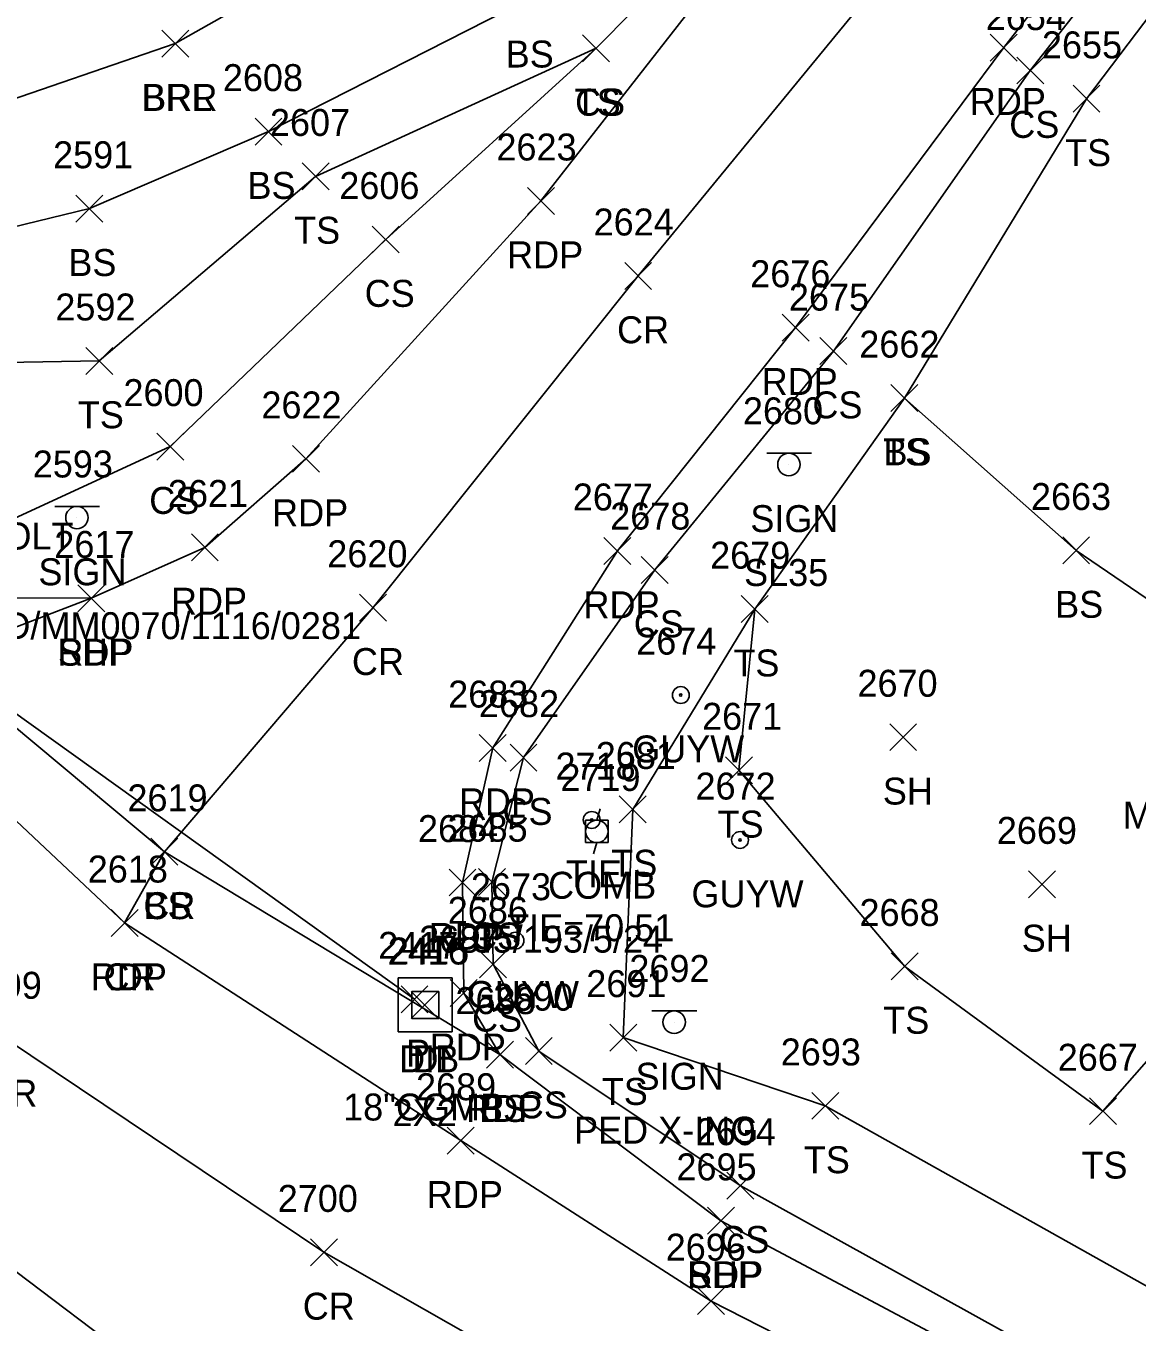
# Model space of a CAD drawing. Extents: x 1504228 to 1506103, y 437717 to 440106.
# Drawn here: x 1505331 to 1505413.5, y 438079.5 to 438175.7 of the extents above; entities that cross this region are included whole.
import ezdxf

# ---------------------------------------------------------------- set-up
doc = ezdxf.new("R2010")
doc.units = 0
for name, color, linetype in [('C_A', 7, 'Continuous'), ('C_C', 7, 'Continuous'), ('C_I', 7, 'Continuous'), ('CBP', 7, 'Continuous'), ('D_A', 7, 'Continuous'), ('D_C', 7, 'Continuous'), ('D_I', 7, 'Continuous'), ('D_TIC', 7, 'Continuous'), ('DCP', 7, 'Continuous'), ('DS', 7, 'Continuous'), ('L_A', 7, 'Continuous'), ('L_C', 7, 'Continuous'), ('L_I', 7, 'Continuous'), ('L_TIC', 7, 'Continuous'), ('LABL', 7, 'Continuous'), ('LELB', 7, 'Continuous'), ('P_A', 7, 'Continuous'), ('P_I', 7, 'Continuous'), ('P_TIC', 7, 'Continuous'), ('PET', 7, 'Continuous'), ('PRC', 7, 'Continuous'), ('PSP', 7, 'Continuous'), ('S_A', 7, 'Continuous'), ('S_C', 7, 'Continuous'), ('S_I', 7, 'Continuous'), ('SSGN', 7, 'Continuous'), ('U_A', 7, 'Continuous'), ('U_C', 7, 'Continuous'), ('U_I', 7, 'Continuous'), ('UP', 7, 'Continuous'), ('UPGW', 7, 'Continuous')]:
    doc.layers.add(name, color=color, linetype=linetype)

msp = doc.modelspace()

# ---------------------------------------------------------------- linework, layer by layer
at = {"layer": 'CBP'}
for radius in [0.625, 0.0833]:
    msp.add_circle((1505372.977, 438116.779), radius, dxfattribs=at)
at = {"layer": 'D_TIC'}
for points in [[(1505358.818, 438102.471), (1505360.818, 438104.471)], [(1505360.818, 438102.471), (1505358.818, 438104.471)], [(1505359.574, 438102.048), (1505361.574, 438104.048)], [(1505361.574, 438102.048), (1505359.574, 438104.048)]]:
    msp.add_lwpolyline(points, dxfattribs=at)
at = {"layer": 'DCP'}
msp.add_lwpolyline([(1505359.818, 438103.471), (1505323.404, 438129.556)], dxfattribs=at)
at = {"layer": 'DS'}
for p, q in [((1505358.613, 438105.05), (1505362.613, 438105.05)), ((1505358.613, 438101.05), (1505358.613, 438105.05)), ((1505362.613, 438105.05), (1505362.613, 438101.05)), ((1505359.613, 438102.05), (1505359.613, 438104.05)), ((1505359.613, 438104.05), (1505361.613, 438104.05)), ((1505361.613, 438104.05), (1505361.613, 438102.05)), ((1505360.618, 438103.052), (1505360.618, 438103.052)), ((1505360.618, 438103.052), (1505360.618, 438103.052)), ((1505361.613, 438102.05), (1505359.613, 438102.05)), ((1505362.613, 438101.05), (1505358.613, 438101.05))]:
    msp.add_line(p, q, dxfattribs=at)
at = {"layer": 'L_TIC'}
for points in [[(1505341.058, 438173.403), (1505343.058, 438175.403)], [(1505343.058, 438173.403), (1505341.058, 438175.403)], [(1505341.058, 438173.403), (1505343.058, 438175.403)], [(1505343.058, 438173.403), (1505341.058, 438175.403)], [(1505372.298, 438173.049), (1505374.298, 438175.049)], [(1505374.298, 438173.049), (1505372.298, 438175.049)], [(1505372.298, 438173.049), (1505374.298, 438175.049)], [(1505374.298, 438173.049), (1505372.298, 438175.049)], [(1505404.53, 438171.403), (1505406.53, 438173.403)], [(1505406.53, 438171.403), (1505404.53, 438173.403)], [(1505408.704, 438169.307), (1505410.704, 438171.307)], [(1505410.704, 438169.307), (1505408.704, 438171.307)], [(1505347.978, 438166.874), (1505349.978, 438168.874)], [(1505349.978, 438166.874), (1505347.978, 438168.874)], [(1505351.472, 438163.545), (1505353.472, 438165.545)], [(1505353.472, 438163.545), (1505351.472, 438165.545)], [(1505334.681, 438161.149), (1505336.681, 438163.149)], [(1505336.681, 438161.149), (1505334.681, 438163.149)], [(1505356.679, 438158.862), (1505358.679, 438160.862)], [(1505358.679, 438158.862), (1505356.679, 438160.862)], [(1505389.919, 438150.584), (1505391.919, 438152.584)], [(1505391.919, 438150.584), (1505389.919, 438152.584)], [(1505335.416, 438149.851), (1505337.416, 438151.851)], [(1505337.416, 438149.851), (1505335.416, 438151.851)], [(1505395.192, 438147.093), (1505397.192, 438149.093)], [(1505397.192, 438147.093), (1505395.192, 438149.093)], [(1505395.192, 438147.093), (1505397.192, 438149.093)], [(1505397.192, 438147.093), (1505395.192, 438149.093)], [(1505340.684, 438143.494), (1505342.684, 438145.494)], [(1505342.684, 438143.494), (1505340.684, 438145.494)], [(1505407.937, 438135.783), (1505409.937, 438137.783)], [(1505409.937, 438135.783), (1505407.937, 438137.783)], [(1505376.655, 438134.332), (1505378.655, 438136.332)], [(1505378.655, 438134.332), (1505376.655, 438136.332)], [(1505384.081, 438131.429), (1505386.081, 438133.429)], [(1505386.081, 438131.429), (1505384.081, 438133.429)], [(1505384.081, 438131.429), (1505386.081, 438133.429)], [(1505386.081, 438131.429), (1505384.081, 438133.429)], [(1505395.097, 438121.922), (1505397.097, 438123.922)], [(1505397.097, 438121.922), (1505395.097, 438123.922)], [(1505366.909, 438120.411), (1505368.909, 438122.411)], [(1505368.909, 438120.411), (1505366.909, 438122.411)], [(1505382.907, 438119.47), (1505384.907, 438121.47)], [(1505384.907, 438119.47), (1505382.907, 438121.47)], [(1505375.016, 438116.564), (1505377.016, 438118.564)], [(1505377.016, 438116.564), (1505375.016, 438118.564)], [(1505340.256, 438113.415), (1505342.256, 438115.415)], [(1505342.256, 438113.415), (1505340.256, 438115.415)], [(1505364.569, 438111.166), (1505366.569, 438113.166)], [(1505366.569, 438111.166), (1505364.569, 438113.166)], [(1505405.409, 438111.003), (1505407.409, 438113.003)], [(1505407.409, 438111.003), (1505405.409, 438113.003)], [(1505364.649, 438105.069), (1505366.649, 438107.069)], [(1505366.649, 438105.069), (1505364.649, 438107.069)], [(1505395.207, 438104.91), (1505397.207, 438106.91)], [(1505397.207, 438104.91), (1505395.207, 438106.91)], [(1505374.312, 438099.628), (1505376.312, 438101.628)], [(1505376.312, 438099.628), (1505374.312, 438101.628)], [(1505368.049, 438098.624), (1505370.049, 438100.624)], [(1505370.049, 438098.624), (1505368.049, 438100.624)], [(1505365.164, 438098.366), (1505367.164, 438100.366)], [(1505367.164, 438098.366), (1505365.164, 438100.366)], [(1505389.313, 438094.558), (1505391.313, 438096.558)], [(1505391.313, 438094.558), (1505389.313, 438096.558)], [(1505409.924, 438094.162), (1505411.924, 438096.162)], [(1505411.924, 438094.162), (1505409.924, 438096.162)], [(1505383, 438088.64), (1505385, 438090.64)], [(1505385, 438088.64), (1505383, 438090.64)]]:
    msp.add_lwpolyline(points, dxfattribs=at)
at = {"layer": 'LABL'}
for points in [[(1505412.94, 438279.434), (1505408.751, 438263.902), (1505393.358, 438239.3), (1505379.992, 438219.583), (1505364.652, 438204.996), (1505342.27, 438194.948), (1505325.182, 438184.758), (1505314.631, 438179.74), (1505312.566, 438178.307), (1505308.953, 438177.263), (1505304.583, 438176.7), (1505296.615, 438175.22), (1505299.292, 438169.398), (1505303.904, 438164.856), (1505308.252, 438160.874), (1505313.047, 438161.473), (1505317.495, 438164.603), (1505327.49, 438169.4), (1505342.058, 438174.403)], [(1505426.709, 438267.128), (1505407.768, 438230.9), (1505394.085, 438210.643), (1505390.776, 438201.917), (1505383.002, 438197.122), (1505370.464, 438191.891), (1505357.673, 438183.248), (1505342.058, 438174.403)]]:
    msp.add_lwpolyline(points, dxfattribs=at)
at = {"layer": 'LELB'}
for points in [[(1505464.371, 438267.578), (1505443.482, 438229.816), (1505429.783, 438207.884), (1505423.465, 438195.212), (1505405.53, 438172.403), (1505390.919, 438151.584), (1505377.655, 438135.332), (1505367.909, 438121.411), (1505365.569, 438112.166), (1505365.649, 438106.069), (1505369.049, 438099.624), (1505384, 438089.64), (1505418.55, 438070.496), (1505425.632, 438075.745)], [(1505470.06, 438267.163), (1505453.418, 438227.384), (1505434.759, 438206.384), (1505425.646, 438191.367), (1505409.704, 438170.307), (1505396.192, 438148.093), (1505385.081, 438132.429), (1505376.016, 438117.564), (1505375.312, 438100.628), (1505390.313, 438095.558), (1505425.632, 438075.745), (1505441.164, 438097.453)], [(1505460.601, 438222.447), (1505449.611, 438199.006), (1505434.468, 438180.022), (1505419.613, 438165.841), (1505418.197, 438153.284), (1505427.495, 438135.49), (1505434.259, 438123.437), (1505428.641, 438123.377), (1505423.022, 438108.926), (1505410.924, 438095.162), (1505396.207, 438105.91), (1505383.907, 438120.47), (1505385.081, 438132.429)], [(1505283.082, 438168.26), (1505293.755, 438159.929), (1505303.056, 438155.723), (1505307.447, 438154.511), (1505318.234, 438150.525), (1505336.416, 438150.851), (1505352.472, 438164.545), (1505373.298, 438174.049), (1505384.454, 438185.345), (1505390.057, 438193.61)], [(1505280.724, 438166.502), (1505281.778, 438166.802), (1505283.082, 438168.26), (1505285.843, 438169.435), (1505295.117, 438166.148), (1505307.071, 438157.841), (1505319.301, 438158.173), (1505335.681, 438162.149), (1505348.978, 438167.874), (1505368.148, 438177.626), (1505382.147, 438186.406), (1505384.268, 438190.42)], [(1505313.175, 438145.226), (1505328.105, 438138.232), (1505341.684, 438144.494), (1505357.679, 438159.862), (1505373.298, 438174.049)], [(1505396.192, 438148.093), (1505408.937, 438136.783), (1505428.641, 438123.377)], [(1505324.098, 438128.725), (1505341.256, 438114.415), (1505366.164, 438099.366)]]:
    msp.add_lwpolyline(points, dxfattribs=at)
at = {"layer": 'P_TIC'}
for points in [[(1505402.557, 438173.106), (1505404.557, 438175.106)], [(1505404.557, 438173.106), (1505402.557, 438175.106)], [(1505368.207, 438161.724), (1505370.207, 438163.724)], [(1505370.207, 438161.724), (1505368.207, 438163.724)], [(1505375.422, 438156.158), (1505377.422, 438158.158)], [(1505377.422, 438156.158), (1505375.422, 438158.158)], [(1505387.105, 438152.318), (1505389.105, 438154.318)], [(1505389.105, 438152.318), (1505387.105, 438154.318)], [(1505350.761, 438142.58), (1505352.761, 438144.58)], [(1505352.761, 438142.58), (1505350.761, 438144.58)], [(1505343.252, 438136.011), (1505345.252, 438138.011)], [(1505345.252, 438136.011), (1505343.252, 438138.011)], [(1505373.877, 438135.75), (1505375.877, 438137.75)], [(1505375.877, 438135.75), (1505373.877, 438137.75)], [(1505334.82, 438132.23), (1505336.82, 438134.23)], [(1505336.82, 438132.23), (1505334.82, 438134.23)], [(1505334.82, 438132.23), (1505336.82, 438134.23)], [(1505336.82, 438132.23), (1505334.82, 438134.23)], [(1505355.739, 438131.535), (1505357.739, 438133.535)], [(1505357.739, 438131.535), (1505355.739, 438133.535)], [(1505364.627, 438121.121), (1505366.627, 438123.121)], [(1505366.627, 438121.121), (1505364.627, 438123.121)], [(1505340.256, 438113.415), (1505342.256, 438115.415)], [(1505342.256, 438113.415), (1505340.256, 438115.415)], [(1505362.383, 438111.135), (1505364.383, 438113.135)], [(1505364.383, 438111.135), (1505362.383, 438113.135)], [(1505337.301, 438108.134), (1505339.301, 438110.134)], [(1505339.301, 438108.134), (1505337.301, 438110.134)], [(1505337.301, 438108.134), (1505339.301, 438110.134)], [(1505339.301, 438108.134), (1505337.301, 438110.134)], [(1505362.469, 438102.928), (1505364.469, 438104.928)], [(1505364.469, 438102.928), (1505362.469, 438104.928)], [(1505365.164, 438098.366), (1505367.164, 438100.366)], [(1505367.164, 438098.366), (1505365.164, 438100.366)], [(1505362.246, 438091.977), (1505364.246, 438093.977)], [(1505364.246, 438091.977), (1505362.246, 438093.977)], [(1505381.569, 438086.03), (1505383.569, 438088.03)], [(1505383.569, 438086.03), (1505381.569, 438088.03)], [(1505381.569, 438086.03), (1505383.569, 438088.03)], [(1505383.569, 438086.03), (1505381.569, 438088.03)], [(1505352.091, 438083.687), (1505354.091, 438085.687)], [(1505354.091, 438083.687), (1505352.091, 438085.687)], [(1505380.83, 438080.07), (1505382.83, 438082.07)], [(1505382.83, 438080.07), (1505380.83, 438082.07)]]:
    msp.add_lwpolyline(points, dxfattribs=at)
at = {"layer": 'PET'}
for points in [[(1505462.284, 438267.741), (1505441.657, 438230.374), (1505428.151, 438208.99), (1505421.287, 438196.87), (1505403.557, 438174.106), (1505388.105, 438153.318), (1505374.877, 438136.75), (1505365.627, 438122.121), (1505363.383, 438112.135), (1505363.469, 438103.928), (1505366.164, 438099.366), (1505382.569, 438087.03)], [(1505311.676, 438134.175), (1505324.098, 438128.725), (1505335.82, 438133.23), (1505344.252, 438137.011), (1505351.761, 438143.58), (1505369.207, 438162.724), (1505390.677, 438190.218), (1505407.619, 438213.727), (1505418.189, 438229.936), (1505438.053, 438265.664)], [(1505219.541, 438139.332), (1505229.478, 438143.453), (1505236.137, 438147.016), (1505243.065, 438149.521), (1505252.019, 438153.342), (1505263.781, 438158.664), (1505277.038, 438164.677), (1505295.889, 438147.093), (1505311.676, 438134.175), (1505338.301, 438109.134), (1505363.246, 438092.977), (1505381.83, 438081.07), (1505419.293, 438061.963), (1505441.952, 438049.929), (1505474.016, 438032.73)], [(1505461.721, 438009.735), (1505401.749, 438041.504), (1505373.571, 438057.173), (1505346.175, 438071.197), (1505322.682, 438088.954), (1505309.586, 438099.121), (1505294.343, 438112.385), (1505276.045, 438129.534)]]:
    msp.add_lwpolyline(points, dxfattribs=at)
at = {"layer": 'PRC'}
for points in [[(1505338.301, 438109.134), (1505341.256, 438114.415), (1505356.739, 438132.535), (1505376.422, 438157.158), (1505399.585, 438185.376), (1505416.016, 438209.597), (1505428.391, 438227.62), (1505451.025, 438266.829)], [(1505263.781, 438158.664), (1505284.158, 438138.68), (1505307.093, 438117.221), (1505329.521, 438100.507), (1505353.091, 438084.687), (1505386.556, 438065.64), (1505412.799, 438050.856), (1505435.687, 438038.531), (1505467.608, 438021.56)]]:
    msp.add_lwpolyline(points, dxfattribs=at)
at = {"layer": 'PSP'}
for points in [[(1505298.089, 438149.32), (1505314.034, 438137.497), (1505323.075, 438133.257), (1505335.82, 438133.23)], [(1505382.569, 438087.03), (1505420.23, 438066.989), (1505444.033, 438054.639), (1505474.002, 438036.682)]]:
    msp.add_lwpolyline(points, dxfattribs=at)
at = {"layer": 'SSGN'}
for p, q in [((1505385.965, 438143.997), (1505389.299, 438143.997)), ((1505387.612, 438143.164), (1505387.612, 438143.164)), ((1505333.113, 438140.051), (1505336.446, 438140.051)), ((1505334.76, 438139.217), (1505334.76, 438139.217)), ((1505377.448, 438102.607), (1505380.781, 438102.607)), ((1505379.094, 438101.773), (1505379.094, 438101.773))]:
    msp.add_line(p, q, dxfattribs=at)
for centre in [(1505387.612, 438143.164), (1505334.76, 438139.217), (1505379.094, 438101.773)]:
    msp.add_circle(centre, 0.833, dxfattribs=at)
at = {"layer": 'UP'}
for p, q in [((1505373.603, 438117.598), (1505373.353, 438116.764)), ((1505372.519, 438115.098), (1505372.519, 438116.764)), ((1505372.519, 438116.764), (1505374.186, 438116.764)), ((1505373.353, 438115.931), (1505373.353, 438115.931)), ((1505374.186, 438116.764), (1505374.186, 438115.098)), ((1505374.186, 438115.098), (1505372.519, 438115.098)), ((1505373.103, 438114.264), (1505373.353, 438115.098))]:
    msp.add_line(p, q, dxfattribs=at)
msp.add_circle((1505373.353, 438115.931), 0.833, dxfattribs=at)
at = {"layer": 'UPGW'}
for centre, radius in [((1505379.585, 438126.048), 0.625), ((1505379.585, 438126.048), 0.0833), ((1505383.986, 438115.292), 0.625), ((1505383.986, 438115.292), 0.0833), ((1505367.314, 438107.821), 0.625), ((1505367.314, 438107.821), 0.0833)]:
    msp.add_circle(centre, radius, dxfattribs=at)

# ---------------------------------------------------------------- texts
at = {"layer": 'C_A'}
msp.add_text('TIE', height=2, dxfattribs=at).set_placement((1505371.056, 438111.779))
at = {"layer": 'C_C'}
for s, p in [('TIE=18.55 CTN N.BOLT', (1505305.447, 438136.852)), ('TIE=70.51', (1505366.693, 438107.779))]:
    msp.add_text(s, height=2, dxfattribs=at).set_placement(p)
at = {"layer": 'C_I'}
msp.add_text('2718', height=2, dxfattribs=at).set_placement((1505370.284, 438119.779))
at = {"layer": 'D_A'}
for s, p in [('P', (1505359.196, 438098.471)), ('DIB', (1505358.677, 438098.048)), ('DI', (1505359.673, 438098.052))]:
    msp.add_text(s, height=2, dxfattribs=at).set_placement(p)
at = {"layer": 'D_C'}
for s, p in [('18"CGMP', (1505354.519, 438094.471)), ('2X2', (1505358.193, 438094.052))]:
    msp.add_text(s, height=2, dxfattribs=at).set_placement(p)
at = {"layer": 'D_I'}
for s, p in [('2417', (1505357.125, 438106.471)), ('2416', (1505357.826, 438106.048)), ('2415', (1505357.925, 438106.052))]:
    msp.add_text(s, height=2, dxfattribs=at).set_placement(p)
at = {"layer": 'L_A'}
for s, p in [('BS', (1505366.589, 438172.626)), ('BRR', (1505339.546, 438169.403)), ('BRL', (1505339.601, 438169.403)), ('TS', (1505371.708, 438169.049)), ('CS', (1505371.739, 438169.049)), ('CS', (1505403.971, 438167.403)), ('TS', (1505408.114, 438165.307)), ('BS', (1505347.419, 438162.874)), ('TS', (1505350.881, 438159.545)), ('BS', (1505334.122, 438157.149)), ('CS', (1505356.12, 438154.862)), ('CS', (1505389.36, 438146.584)), ('TS', (1505334.826, 438145.851)), ('TS', (1505394.601, 438143.093)), ('BS', (1505394.633, 438143.093)), ('CS', (1505340.125, 438139.494)), ('BS', (1505407.378, 438131.783)), ('CS', (1505376.096, 438130.332)), ('TS', (1505383.491, 438127.429)), ('TS', (1505383.491, 438127.429)), ('SH', (1505394.586, 438117.922)), ('CS', (1505366.35, 438116.411)), ('TS', (1505382.316, 438115.47)), ('TS', (1505374.425, 438112.564)), ('BS', (1505339.697, 438109.415)), ('CS', (1505364.01, 438107.166)), ('SH', (1505404.897, 438107.003)), ('CS', (1505364.09, 438101.069)), ('TS', (1505394.617, 438100.91)), ('TS', (1505373.722, 438095.628)), ('CS', (1505367.49, 438094.624)), ('BS', (1505364.605, 438094.366)), ('TS', (1505388.722, 438090.558)), ('TS', (1505409.333, 438090.162)), ('CS', (1505382.441, 438084.64))]:
    msp.add_text(s, height=2, dxfattribs=at).set_placement(p)
at = {"layer": 'L_C'}
msp.add_text('M.SPRUCE', height=2, dxfattribs=at).set_placement((1505412.404, 438116.123))
at = {"layer": 'L_I'}
for s, p in [('2654', (1505402.223, 438175.403)), ('2655', (1505406.397, 438173.307)), ('2608', (1505345.592, 438170.874)), ('2607', (1505349.086, 438167.545)), ('2591', (1505332.988, 438165.149)), ('2606', (1505354.238, 438162.862)), ('2675', (1505387.612, 438154.584)), ('2592', (1505333.157, 438153.851)), ('2662', (1505392.837, 438151.093)), ('2662', (1505392.837, 438151.093)), ('2600', (1505338.211, 438147.494)), ('2663', (1505405.583, 438139.783)), ('2678', (1505374.348, 438138.332)), ('2679', (1505381.766, 438135.429)), ('2679', (1505381.766, 438135.429)), ('2670', (1505392.704, 438125.922)), ('2682', (1505364.602, 438124.411)), ('2671', (1505381.166, 438123.47)), ('2681', (1505373.275, 438120.564)), ('2619', (1505338.508, 438117.415)), ('2685', (1505362.262, 438115.166)), ('2669', (1505403.047, 438115.003)), ('2686', (1505362.287, 438109.069)), ('2668', (1505392.853, 438108.91)), ('2691', (1505372.572, 438103.628)), ('2688', (1505362.857, 438102.366)), ('2690', (1505365.656, 438102.624)), ('2693', (1505387.006, 438098.558)), ('2667', (1505407.569, 438098.162)), ('2694', (1505380.693, 438092.64))]:
    msp.add_text(s, height=2, dxfattribs=at).set_placement(p)
at = {"layer": 'P_A'}
for s, p in [('RDP', (1505401.045, 438169.106)), ('RDP', (1505366.695, 438157.724)), ('CR', (1505374.856, 438152.158)), ('RDP', (1505385.593, 438148.318)), ('RDP', (1505349.249, 438138.58)), ('RDP', (1505341.74, 438132.011)), ('RDP', (1505372.365, 438131.75)), ('SHP', (1505333.356, 438128.23)), ('RDP', (1505333.308, 438128.23)), ('CR', (1505355.172, 438127.535)), ('RDP', (1505363.115, 438117.121)), ('CR', (1505339.689, 438109.415)), ('RDP', (1505360.871, 438107.135)), ('RDP', (1505335.789, 438104.134)), ('CR', (1505336.734, 438104.134)), ('RDP', (1505360.957, 438098.928)), ('CR', (1505327.955, 438095.507)), ('RDP', (1505363.652, 438094.366)), ('RDP', (1505360.735, 438087.977)), ('SHP', (1505380.105, 438082.03)), ('RDP', (1505380.058, 438082.03)), ('CR', (1505351.524, 438079.687))]:
    msp.add_text(s, height=2, dxfattribs=at).set_placement(p)
at = {"layer": 'P_I'}
for s, p in [('2623', (1505365.9, 438165.724)), ('2624', (1505373.115, 438160.158)), ('2676', (1505384.743, 438156.318)), ('2622', (1505348.454, 438146.58)), ('2621', (1505341.512, 438140.011)), ('2677', (1505371.57, 438139.75)), ('2617', (1505333.08, 438136.23)), ('2617', (1505333.08, 438136.23)), ('2620', (1505353.345, 438135.535)), ('2683', (1505362.32, 438125.121)), ('2619', (1505338.508, 438117.415)), ('2684', (1505360.076, 438115.135)), ('2618', (1505335.561, 438112.134)), ('2618', (1505335.561, 438112.134)), ('2687', (1505360.162, 438106.928)), ('2699', (1505326.206, 438103.507)), ('2688', (1505362.857, 438102.366)), ('2689', (1505359.931, 438095.977)), ('2695', (1505379.262, 438090.03)), ('2695', (1505379.262, 438090.03)), ('2700', (1505349.666, 438087.687)), ('2696', (1505378.468, 438084.07))]:
    msp.add_text(s, height=2, dxfattribs=at).set_placement(p)
at = {"layer": 'S_A'}
for p in [(1505384.75, 438138.143), (1505331.898, 438134.197), (1505376.232, 438096.753)]:
    msp.add_text('SIGN', height=2, dxfattribs=at).set_placement(p)
at = {"layer": 'S_C'}
for s, p in [('SL35', (1505384.285, 438134.143)), ('STOP/OXBOW RD/MM0070/1116/0281', (1505308.425, 438130.197)), ('PED X-ING', (1505371.665, 438092.753))]:
    msp.add_text(s, height=2, dxfattribs=at).set_placement(p)
at = {"layer": 'S_I'}
for s, p in [('2680', (1505384.199, 438146.143)), ('2593', (1505331.48, 438142.197)), ('2692', (1505375.768, 438104.753))]:
    msp.add_text(s, height=2, dxfattribs=at).set_placement(p)
at = {"layer": 'U_A'}
for s, p in [('GUYW', (1505375.979, 438121.048)), ('COMB', (1505369.738, 438110.931)), ('GUYW', (1505380.38, 438110.292)), ('GUYW', (1505363.708, 438102.821))]:
    msp.add_text(s, height=2, dxfattribs=at).set_placement(p)
at = {"layer": 'U_C'}
msp.add_text('35/193/5/24', height=2, dxfattribs=at).set_placement((1505364.14, 438106.931))
at = {"layer": 'U_I'}
for s, p in [('2674', (1505376.278, 438129.048)), ('2719', (1505370.652, 438118.931)), ('2672', (1505380.679, 438118.292)), ('2673', (1505364.007, 438110.821))]:
    msp.add_text(s, height=2, dxfattribs=at).set_placement(p)

doc.saveas('drawing.dxf')
